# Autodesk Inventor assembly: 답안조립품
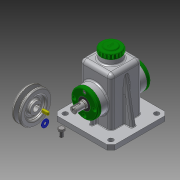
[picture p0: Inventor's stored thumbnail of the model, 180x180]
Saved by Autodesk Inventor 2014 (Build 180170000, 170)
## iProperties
Created: 2017-08
Part Number: 답안조립품
Document SubType Name: Assembly
Designer: user
Author: user
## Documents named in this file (14)
- D:\470825V1003\답안조립품.iam
- D:\470825V1003\본체.ipt
- D:\470825V1003\뒤커버.ipt
- D:\470825V1003\베어링 15 x 35 x 11.ipt
- D:\470825V1003\멈춤링 15 x 1.ipt
- D:\470825V1003\상부캡.ipt
- D:\470825V1003\앞커버.ipt
- D:\470825V1003\오일실 15 25 7.ipt
- D:\470825V1003\축.ipt
- D:\470825V1003\V-벨트풀리.ipt
- D:\470825V1003\볼트 M4 x 10.ipt
- D:\470825V1003\볼트 M6 x 12.ipt
- D:\470825V1003\키 5 x 5 x 14.ipt
- D:\470825V1003\와셔.ipt
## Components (1 placed, 1 different names)
1. V-벨트풀리:1
